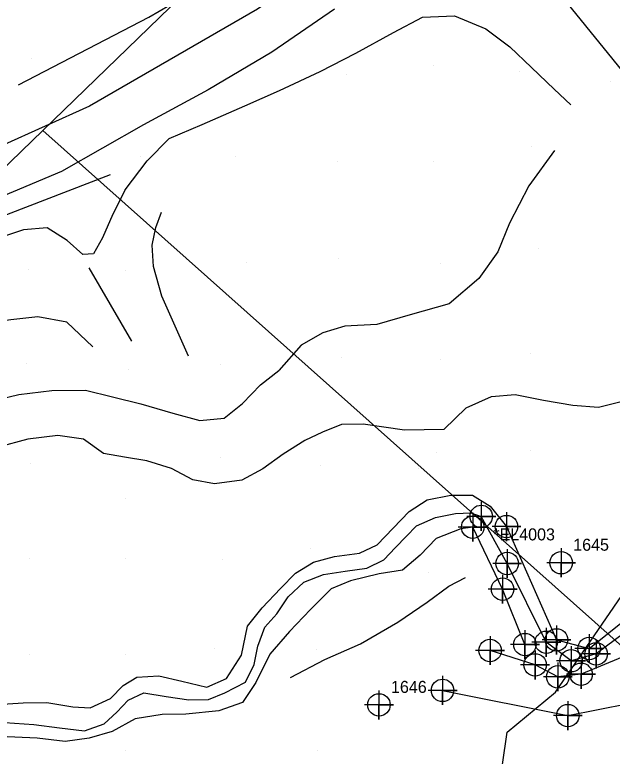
# Model space of a CAD drawing. Extents: x 1497074 to 1501343, y 481943 to 486114.
# Drawn here: x 1498180.6 to 1498304.9, y 484641.5 to 484795.7 of the extents above; entities that cross this region are included whole.
import ezdxf

# ---------------------------------------------------------------- set-up
doc = ezdxf.new("R2010")
doc.units = 0
for name, color, linetype in [('Exist DTM Breakline', 7, 'Continuous'), ('Exist DTM Breakline Cogo Point CELL', 7, 'Continuous'), ('Exist DTM Drainline', 7, 'Continuous'), ('Exist DTM Drainline Cogo Comment', 7, 'Continuous'), ('Exist DTM Drainline Cogo Point CELL', 7, 'Continuous'), ('Exist DTM Regular Point CELL', 7, 'Continuous'), ('Exist DTM Regular Point Cogo Number', 7, 'Continuous'), ('PH Exist DTM Boundary', 7, 'Continuous'), ('PH Exist DTM Breakline', 7, 'Continuous'), ('PH Exist DTM Obscure Area', 7, 'Continuous'), ('PH Exist DTM Point', 7, 'Continuous')]:
    doc.layers.add(name, color=color, linetype=linetype)

msp = doc.modelspace()

# ---------------------------------------------------------------- linework, layer by layer
at = {"layer": 'Exist DTM Breakline'}
for points in [[(1498282.88, 484689.25), (1498293.31, 484665.67), (1498300.1, 484663.88), (1498316.97, 484677.35), (1498319.45, 484684.03), (1498325.18, 484690.36), (1498331.14, 484692.46)], [(1498286.74, 484664.7), (1498282.09, 484676.22), (1498275.86, 484689.14)], [(1498324.33, 484678.54), (1498308.15, 484662.57), (1498298.41, 484658.52), (1498293.57, 484658), (1498288.84, 484660.47), (1498279.47, 484663.46)], [(1498269.6, 484655.18), (1498295.66, 484649.92), (1498314.57, 484653.72), (1498329.33, 484673.43)]]:
    msp.add_lwpolyline(points, dxfattribs=at)
at = {"layer": 'Exist DTM Breakline Cogo Point CELL'}
for points in [[(1498275.86, 484692.14), (1498275.86, 484686.14), (1498275.86, 484689.14), (1498278.86, 484689.14), (1498272.86, 484689.14)], [(1498282.88, 484692.25), (1498282.88, 484686.25), (1498282.88, 484689.25), (1498285.88, 484689.25), (1498279.88, 484689.25)], [(1498282.09, 484679.22), (1498282.09, 484673.22), (1498282.09, 484676.22), (1498285.09, 484676.22), (1498279.09, 484676.22)], [(1498293.31, 484668.67), (1498293.31, 484662.67), (1498293.31, 484665.67), (1498296.31, 484665.67), (1498290.31, 484665.67)], [(1498279.47, 484666.46), (1498279.47, 484660.46), (1498279.47, 484663.46), (1498282.47, 484663.46), (1498276.47, 484663.46)], [(1498286.74, 484667.7), (1498286.74, 484661.7), (1498286.74, 484664.7), (1498289.74, 484664.7), (1498283.74, 484664.7)], [(1498300.1, 484666.88), (1498300.1, 484660.88), (1498300.1, 484663.88), (1498303.1, 484663.88), (1498297.1, 484663.88)], [(1498288.84, 484663.47), (1498288.84, 484657.47), (1498288.84, 484660.47), (1498291.84, 484660.47), (1498285.84, 484660.47)], [(1498293.57, 484661), (1498293.57, 484655), (1498293.57, 484658), (1498296.57, 484658), (1498290.57, 484658)], [(1498298.41, 484661.52), (1498298.41, 484655.52), (1498298.41, 484658.52), (1498301.41, 484658.52), (1498295.41, 484658.52)], [(1498269.6, 484658.18), (1498269.6, 484652.18), (1498269.6, 484655.18), (1498272.6, 484655.18), (1498266.6, 484655.18)], [(1498295.66, 484652.92), (1498295.66, 484646.92), (1498295.66, 484649.92), (1498298.66, 484649.92), (1498292.66, 484649.92)]]:
    msp.add_lwpolyline(points, dxfattribs=at)
for centre in [(1498275.86, 484689.14), (1498282.88, 484689.25), (1498282.09, 484676.22), (1498293.31, 484665.67), (1498286.74, 484664.7), (1498279.47, 484663.46), (1498300.1, 484663.88), (1498288.84, 484660.47), (1498293.57, 484658), (1498298.41, 484658.52), (1498269.6, 484655.18), (1498295.66, 484649.92)]:
    msp.add_circle(centre, 2.34, dxfattribs=at)
at = {"layer": 'Exist DTM Drainline'}
msp.add_lwpolyline([(1498429.82, 484721.4), (1498419.42, 484722.03), (1498410.04, 484716.18), (1498396.88, 484705.24), (1498379.28, 484694.51), (1498368.9, 484683.3), (1498365.1, 484682.53), (1498351.6, 484689.55), (1498337.41, 484687.35), (1498327.92, 484689.08), (1498319.22, 484675.88), (1498301.55, 484662.75), (1498296.33, 484661.35), (1498291.18, 484665.18), (1498283.03, 484681.58), (1498277.65, 484691.38)], dxfattribs=at)
at = {"layer": 'Exist DTM Drainline Cogo Point CELL'}
for points in [[(1498277.65, 484694.38), (1498277.65, 484688.38), (1498277.65, 484691.38), (1498280.65, 484691.38), (1498274.65, 484691.38)], [(1498283.03, 484684.58), (1498283.03, 484678.58), (1498283.03, 484681.58), (1498286.03, 484681.58), (1498280.03, 484681.58)], [(1498291.18, 484668.18), (1498291.18, 484662.18), (1498291.18, 484665.18), (1498294.18, 484665.18), (1498288.18, 484665.18)], [(1498301.55, 484665.75), (1498301.55, 484659.75), (1498301.55, 484662.75), (1498304.55, 484662.75), (1498298.55, 484662.75)], [(1498296.33, 484664.35), (1498296.33, 484658.35), (1498296.33, 484661.35), (1498299.33, 484661.35), (1498293.33, 484661.35)]]:
    msp.add_lwpolyline(points, dxfattribs=at)
for centre in [(1498277.65, 484691.38), (1498283.03, 484681.58), (1498291.18, 484665.18), (1498301.55, 484662.75), (1498296.33, 484661.35)]:
    msp.add_circle(centre, 2.34, dxfattribs=at)
at = {"layer": 'Exist DTM Regular Point CELL'}
for points in [[(1498294.28, 484684.73), (1498294.28, 484678.73), (1498294.28, 484681.73), (1498297.28, 484681.73), (1498291.28, 484681.73)], [(1498256.36, 484655.15), (1498256.36, 484649.15), (1498256.36, 484652.15), (1498259.36, 484652.15), (1498253.36, 484652.15)]]:
    msp.add_lwpolyline(points, dxfattribs=at)
for centre in [(1498294.28, 484681.73), (1498256.36, 484652.15)]:
    msp.add_circle(centre, 2.34, dxfattribs=at)
at = {"layer": 'PH Exist DTM Boundary'}
for points in [[(1498186.43, 484771.69), (1498560.82, 484438.23), (1498782.89, 484653.31), (1498924.23, 484841.06), (1498545.19, 485168.9), (1498406.94, 484985.26)], [(1497810.36, 484407.45), (1498181.14, 484070.49), (1498560.82, 484438.23), (1498186.43, 484771.69)]]:
    msp.add_lwpolyline(points, close=True, dxfattribs=at)
at = {"layer": 'PH Exist DTM Breakline'}
for points in [[(1498181.37, 484781.18), (1498208.49, 484795.23), (1498223.54, 484804.07), (1498233.75, 484810.73), (1498244.68, 484818.76), (1498263.82, 484834.08), (1498278.02, 484847.32), (1498281.72, 484851.83), (1498298.66, 484869.83), (1498301.45, 484871.68), (1498307.29, 484877.63), (1498329, 484901.41), (1498350.54, 484925.65), (1498370.84, 484949.29), (1498384.88, 484964.92), (1498389.81, 484971.37), (1498392.74, 484978.39), (1498393.42, 484984.31), (1498393.63, 484989.96)], [(1498409.44, 484976.25), (1498390.25, 484956.11), (1498357.73, 484919.21), (1498328.64, 484885.71), (1498293.98, 484849.18), (1498276.56, 484831.76), (1498265.93, 484822.19), (1498250.58, 484810.54), (1498231.07, 484796.87), (1498196.13, 484776.72)], [(1498357.29, 484754.77), (1498359.24, 484752.36), (1498343.24, 484739.73), (1498327.61, 484759.07), (1498309.91, 484780.52), (1498294.59, 484799.39), (1498283.42, 484812.17), (1498280.07, 484815.31), (1498276.09, 484818.03)], [(1498247.11, 484796.9), (1498234.03, 484787.94), (1498220.84, 484780.15), (1498207.34, 484772.83)], [(1498203.57, 484759.33), (1498208.12, 484765.34), (1498212.73, 484769.97), (1498219.58, 484772.88), (1498228.47, 484776.81), (1498235.66, 484779.97), (1498244.13, 484783.96), (1498251.52, 484787.74), (1498259.41, 484792.07), (1498265.39, 484795.24), (1498272.11, 484795.49), (1498278.61, 484792.79), (1498283.59, 484789.04), (1498288.11, 484784.75), (1498292.81, 484780.29), (1498296.3, 484776.97)], [(1498196.13, 484776.72), (1498177.7, 484768.41), (1498157.43, 484759.82), (1498129.86, 484749.45)], [(1498207.34, 484772.83), (1498190.3, 484763.13), (1498170.08, 484754.67), (1498137.8, 484742.6), (1498117.32, 484735.12)], [(1498292.86, 484767.47), (1498287.52, 484760.15), (1498283.53, 484752.41), (1498281.11, 484746.42), (1498277.15, 484740.87), (1498270.94, 484735.58), (1498262.86, 484733.29), (1498255.94, 484731.3), (1498249.27, 484730.92), (1498244.68, 484729.58), (1498240.19, 484727.02), (1498235.53, 484721.72)], [(1498117.15, 484730.25), (1498148.45, 484742.47), (1498200.46, 484762.51)], [(1498203.57, 484759.33), (1498200.97, 484754.27), (1498198.8, 484749.33), (1498196.98, 484746), (1498194.75, 484745.86), (1498191.5, 484748.79), (1498187.34, 484751.42), (1498182.38, 484751.02), (1498176.73, 484749.14), (1498170.33, 484746.99), (1498164.07, 484744.27), (1498157.92, 484741.58), (1498152.11, 484739.12), (1498147.75, 484734.6), (1498142.67, 484731.65), (1498135.39, 484731.17), (1498128.82, 484730.54), (1498123.71, 484728.26)], [(1498216.69, 484724.69), (1498211.16, 484737.16), (1498209.43, 484743.35), (1498209.13, 484747.8), (1498209.91, 484751.46), (1498211.07, 484754.66)], [(1498195.99, 484743.08), (1498204.83, 484727.86)], [(1498196.78, 484726.66), (1498191.37, 484731.78), (1498185.39, 484732.91), (1498179.76, 484732.24), (1498172.42, 484731.16), (1498165.43, 484730.64), (1498157.29, 484728.82), (1498148.65, 484725.52), (1498140.3, 484722.55), (1498133.24, 484719.81), (1498126.61, 484717.38), (1498119.8, 484714.72), (1498113.81, 484709.78), (1498109.56, 484705.33)], [(1498269.88, 484709.47), (1498274.5, 484713.94), (1498279.79, 484716.29), (1498284.72, 484716.72), (1498290.58, 484715.56), (1498296.68, 484714.5), (1498302.03, 484714.12), (1498308.44, 484715.7), (1498312.94, 484718.37), (1498317.08, 484720.14), (1498322.49, 484721.64), (1498328.91, 484722.11), (1498334.34, 484721.22), (1498339.21, 484719.59), (1498344.41, 484717.28), (1498349.09, 484715.14)], [(1498151.33, 484700.12), (1498157.66, 484705.53), (1498163.65, 484709.73), (1498170.35, 484713.18), (1498175.03, 484715.2), (1498181.45, 484716.7), (1498188.29, 484717.57), (1498195.3, 484717.65), (1498200.93, 484716.28), (1498206.81, 484714.8), (1498213.45, 484712.87), (1498219.06, 484711.31), (1498224.17, 484711.84), (1498227.97, 484714.84), (1498231.69, 484718.71), (1498235.53, 484721.72)], [(1498269.88, 484709.47), (1498261.67, 484709.31), (1498253.05, 484710.56), (1498248.56, 484710.46), (1498244.59, 484708.88), (1498240.91, 484707.15), (1498236.45, 484704.34), (1498232.22, 484701.24), (1498227.83, 484698.93), (1498222.1, 484698.13), (1498217.63, 484699.01), (1498213.21, 484701.35), (1498208.07, 484702.93), (1498203.38, 484703.72), (1498199.01, 484704.44), (1498194.89, 484707.42), (1498189.51, 484708.22), (1498183.3, 484707.42), (1498177.06, 484705.79), (1498171.07, 484704.14), (1498166.03, 484700.5), (1498161.66, 484695.92)], [(1498176.92, 484652.21), (1498182.33, 484652.55), (1498187.24, 484652.66), (1498192.66, 484651.74), (1498196.26, 484651.51), (1498200.52, 484653.49), (1498203.13, 484656.22), (1498205.96, 484657.92), (1498210.52, 484658.17), (1498215.34, 484657.07), (1498220.57, 484655.85), (1498224.63, 484657.66), (1498227.76, 484662.53), (1498228.99, 484668.55), (1498232.08, 484672.34), (1498235.9, 484676.36), (1498238.98, 484679.59), (1498242.72, 484681.82), (1498247.13, 484683.06), (1498252.33, 484683.7), (1498256, 484685.45), (1498259.29, 484688.89), (1498262.65, 484692.41), (1498266.37, 484694.81), (1498271.34, 484695.82), (1498275.85, 484695.76), (1498279.5, 484693.48), (1498282.88, 484689.25)], [(1498178.51, 484648.46), (1498184.54, 484648.11), (1498189.87, 484647.4), (1498195.08, 484646.77), (1498199.18, 484648.24), (1498201.79, 484650.64), (1498204.16, 484653.13), (1498207.42, 484654.63), (1498212.09, 484653.92), (1498216.77, 484653.24), (1498220.91, 484653.25), (1498224.25, 484654.66), (1498228.61, 484656.87), (1498230.37, 484660.56), (1498231.16, 484664.39), (1498232.64, 484668.34), (1498235.09, 484671.09), (1498237.45, 484674.61), (1498240.74, 484677.68), (1498244.82, 484679.31), (1498249.34, 484679.99), (1498253.81, 484680.57), (1498257.37, 484682.33), (1498259.81, 484684.87), (1498262.03, 484687.19), (1498264.19, 484689.38), (1498268.12, 484691.15), (1498272.29, 484691.95), (1498275.49, 484692.08), (1498277.65, 484691.38)], [(1498275.86, 484689.14), (1498273.41, 484688.8), (1498268.29, 484686.8), (1498264.9, 484683.28), (1498261.28, 484680.17), (1498256.39, 484679.42), (1498250.4, 484677.96), (1498246.42, 484676.3), (1498242.09, 484672), (1498237.71, 484667.41), (1498233.64, 484662.72), (1498230.73, 484656.79), (1498227.96, 484652.62), (1498223.05, 484650.95), (1498216.17, 484650.21), (1498211.25, 484650.13), (1498205.62, 484649.28), (1498200.83, 484646.62), (1498196.06, 484645.21), (1498191.08, 484644.51), (1498185.23, 484645.26), (1498177.41, 484645.61)], [(1498237.95, 484657.82), (1498245.11, 484661.59), (1498252.53, 484664.86), (1498260.31, 484669.34), (1498266.42, 484673.5), (1498270.87, 484676.84), (1498274.35, 484678.68)]]:
    msp.add_lwpolyline(points, dxfattribs=at)
at = {"layer": 'PH Exist DTM Obscure Area'}
msp.add_lwpolyline([(1498355.63, 484632.52), (1498290.68, 484570.04), (1498257.3, 484537.58), (1498250.31, 484532.74), (1498247.22, 484535.69), (1498242.12, 484540.68), (1498249.39, 484548.29), (1498258.26, 484557.58), (1498264.88, 484564.52), (1498267.78, 484576.18), (1498266.58, 484587.34), (1498261.75, 484599.27), (1498263.15, 484609.32), (1498271.1, 484617.66), (1498279.29, 484626.23), (1498284.85, 484632.06), (1498282.05, 484639.76), (1498283.05, 484646.51), (1498293.08, 484654.8), (1498307.67, 484676.05)], dxfattribs=at)
at = {"layer": 'PH Exist DTM Point'}
for p, q in [((1498184.09, 484786.54), (1498184.09, 484786.54)), ((1498267.81, 484785.16), (1498267.81, 484785.16)), ((1498285.66, 484783.97), (1498285.66, 484783.97)), ((1498249.7, 484783.37), (1498249.7, 484783.37)), ((1498304.62, 484781.79), (1498304.62, 484781.79)), ((1498288.05, 484768.31), (1498288.05, 484768.31)), ((1498206.63, 484766.2), (1498206.63, 484766.2)), ((1498226.57, 484766.34), (1498226.57, 484766.34)), ((1498247.81, 484765.16), (1498247.81, 484765.16)), ((1498267.81, 484765.16), (1498267.81, 484765.16)), ((1498289.59, 484747.03), (1498289.59, 484747.03)), ((1498228.75, 484744.27), (1498228.75, 484744.27)), ((1498247.9, 484745.07), (1498247.9, 484745.07)), ((1498269.06, 484743.98), (1498269.06, 484743.98)), ((1498183.37, 484742.84), (1498183.37, 484742.84)), ((1498203.66, 484742.56), (1498203.66, 484742.56)), ((1498287.81, 484725.16), (1498287.81, 484725.16)), ((1498248.48, 484724.53), (1498248.48, 484724.53)), ((1498269.07, 484723.97), (1498269.07, 484723.97)), ((1498182.95, 484723.23), (1498182.95, 484723.23)), ((1498223.3, 484722.9), (1498223.3, 484722.9)), ((1498204.33, 484721.92), (1498204.33, 484721.92)), ((1498287.81, 484705.16), (1498287.81, 484705.16)), ((1498223.38, 484703.6), (1498223.38, 484703.6)), ((1498268.42, 484704.58), (1498268.42, 484704.58)), ((1498183.78, 484702.44), (1498183.78, 484702.44)), ((1498244.26, 484701.99), (1498244.26, 484701.99)), ((1498264.58, 484701.34), (1498264.58, 484701.34)), ((1498203.68, 484695.12), (1498203.68, 484695.12)), ((1498242.19, 484684.6), (1498242.19, 484684.6)), ((1498183.61, 484682.6), (1498183.61, 484682.6)), ((1498203.61, 484682.6), (1498203.61, 484682.6)), ((1498223.74, 484682.48), (1498223.74, 484682.48)), ((1498266.7, 484679.66), (1498266.7, 484679.66)), ((1498222.21, 484663.94), (1498222.21, 484663.94)), ((1498243.34, 484663.77), (1498243.34, 484663.77)), ((1498183.61, 484662.6), (1498183.61, 484662.6)), ((1498203.61, 484662.6), (1498203.61, 484662.6)), ((1498203.61, 484642.6), (1498203.61, 484642.6)), ((1498243.61, 484642.6), (1498243.61, 484642.6))]:
    msp.add_line(p, q, dxfattribs=at)

# ---------------------------------------------------------------- texts
at = {"layer": 'Exist DTM Drainline Cogo Comment'}
msp.add_text('*EL4003', height=2.5, dxfattribs=at).set_placement((1498280.15, 484686.38))
at = {"layer": 'Exist DTM Regular Point Cogo Number'}
for s, p in [('1645', (1498296.78, 484684.23)), ('1646', (1498258.86, 484654.65))]:
    msp.add_text(s, height=2.5, dxfattribs=at).set_placement(p)

doc.saveas('drawing.dxf')
